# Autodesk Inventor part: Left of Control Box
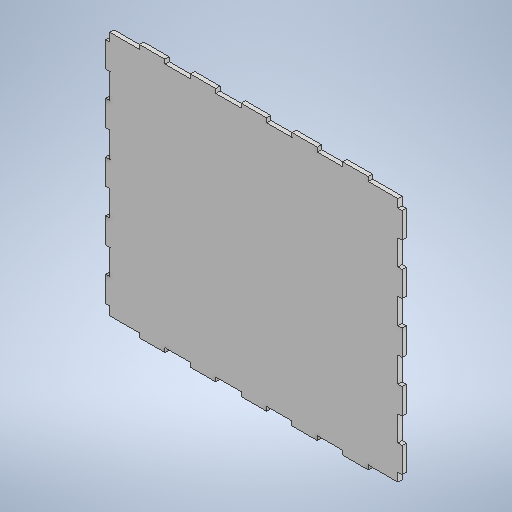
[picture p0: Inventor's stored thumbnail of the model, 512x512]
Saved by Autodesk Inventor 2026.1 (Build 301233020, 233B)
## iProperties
Created: 2026-11
Part Number: Left of Control Box
Material: Generic
Document SubType Name: Modeling
Designer: hp
Density: 1 g/cm^3
Appearance: Default
Author: hp
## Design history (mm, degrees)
sketch "Sketch1"
  geometry: L1 (130, 5)-(130, 0); L2 (130, 5)-(130, 0); L3 (130, 0)-(100, 0); L4 (100, 0)-(100, 5); L5 (130, 0)-(100, 0); L6 (100, 0)-(100, 5); L7 (100, 5)-(130, 5); L8 (100, 5)-(130, 5); L9 (160, 0)-(160, 5); L10 (160, 0)-(160, 5); L11 (190, 0)-(160, 0); L12 (160, 5)-(190, 5); L13 (190, 0)-(160, 0); L14 (160, 5)-(190, 5); L15 (190, 5)-(190, 0); L16 (0, 300)-(350, 300); L17 (350, 300)-(350, 0); L18 (350, 0)-(0, 0); L19 (0, 0)-(0, 300); L20 (70, 5)-(70, 0); L21 (70, 0)-(40, 0); L22 (40, 0)-(40, 5); L23 (40, 5)-(70, 5); L24 (175, 300)-(175, 0); L25 (350, 150)-(0, 150); L26 (220, 0)-(220, 5); L27 (220, 0)-(220, 5); L28 (250, 0)-(220, 0); L29 (250, 0)-(220, 0); L30 (220, 5)-(250, 5); L31 (250, 5)-(250, 0); L32 (280, 0)-(280, 5); L33 (310, 5)-(310, 0); L34 (280, 5)-(310, 5); L35 (310, 0)-(280, 0); L36 (190, 5)-(190, 0); L37 (160, 300)-(160, 295); L38 (160, 300)-(160, 295); L39 (160, 300)-(160, 295); L40 (160, 295)-(190, 295); L41 (160, 295)-(190, 295); L42 (190, 300)-(160, 300); L43 (190, 300)-(160, 300); L44 (190, 295)-(190, 300); L45 (190, 295)-(190, 300); L46 (250, 295)-(250, 300); L47 (220, 300)-(220, 295); L48 (220, 300)-(220, 295); L49 (250, 300)-(220, 300); L50 (220, 295)-(250, 295); L51 (250, 300)-(220, 300); L52 (220, 295)-(250, 295); L53 (250, 295)-(250, 300); L54 (280, 300)-(280, 295); L55 (280, 295)-(310, 295); L56 (310, 300)-(280, 300); L57 (310, 295)-(310, 300); L58 (220, 5)-(250, 5); L59 (250, 5)-(250, 0); L60 (190, 5)-(190, 0); L61 (160, 0)-(160, 5); L62 (190, 0)-(160, 0); L63 (160, 5)-(190, 5); L64 (100, 300)-(100, 295)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; 113 further points
  constraints: 308 end point, 90 symmetric about line, 8 parallel, 6 midpoint, 5 horizontal, 4 perpendicular, 2 vertical, 1 coincident, 1 point on line, 147 other
  dimensions: "d14" = 350 distance of L17.end L18.end; "d15" = 300 distance of L16.end L17.end; "d16" = 30 distance of L9.end L12.end; "d17" = 5 distance of L9.start L9.end; "d18" = 60 distance of L11.start L1.end; "d19" = 60 distance of L11.start L28.start; "d20" = 5 distance of L97.end L96.end; "d21" = 30 distance of L96.end L95.end; "d22" = 60 distance of L95.end L83.end; "d23" = 60 distance of L95.end L107.end; "d24" = 5 distance between parallel lines of L16 L151
extrude "Extrusion2" new body sketch "Sketch1" distance "d25" = 5; taper "d26" = 0 deg
body "Solid2"
node "Sketch Rectangular Pattern2" dims "d18" = 60, "d19" = 60
node "Sketch Rectangular Pattern4" dims "d22" = 60, "d23" = 60
